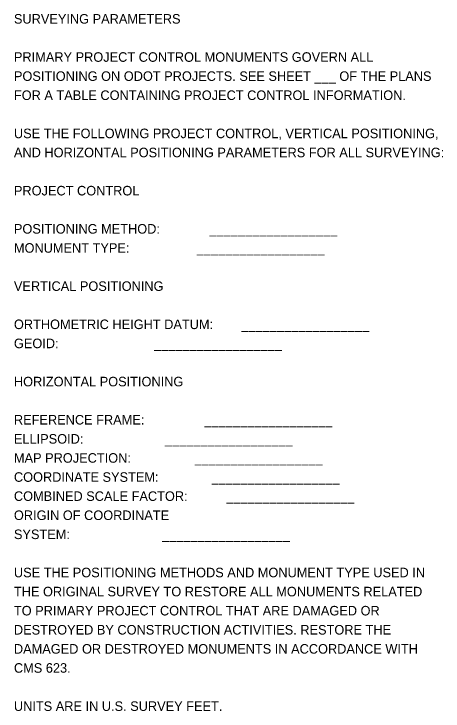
# Model space of a CAD drawing. Extents: x -6.7 to 44.8, y 0 to 42.6.
# Drawn here: x 38.55 to 44.85, y 32.38 to 42.6 of the extents above; entities that cross this region are included whole.
import ezdxf

# ---------------------------------------------------------------- set-up
doc = ezdxf.new("R2010")
doc.units = 0
doc.layers.add('SH_Text', color=7, linetype='Continuous')

msp = doc.modelspace()

# ---------------------------------------------------------------- texts
at = {"layer": 'SH_Text'}
for s, p in [('SURVEYING PARAMETERS', (38.553, 42.462)), ('PRIMARY PROJECT CONTROL MONUMENTS GOVERN ALL', (38.553, 41.902)), ('POSITIONING ON ODOT PROJECTS. SEE SHEET ___ OF THE PLANS', (38.553, 41.622)), ('FOR A TABLE CONTAINING PROJECT CONTROL INFORMATION.', (38.553, 41.342)), ('USE THE FOLLOWING PROJECT CONTROL, VERTICAL POSITIONING,', (38.553, 40.782)), ('AND HORIZONTAL POSITIONING PARAMETERS FOR ALL SURVEYING:', (38.553, 40.502)), ('PROJECT CONTROL', (38.553, 39.942)), ('POSITIONING METHOD:              __________________', (38.553, 39.382)), ('MONUMENT TYPE:                   __________________', (38.553, 39.102)), ('VERTICAL POSITIONING', (38.553, 38.542)), ('ORTHOMETRIC HEIGHT DATUM:        __________________', (38.553, 37.982)), ('GEOID:                           __________________', (38.553, 37.702)), ('HORIZONTAL POSITIONING', (38.553, 37.142)), ('REFERENCE FRAME:                 __________________', (38.553, 36.582)), ('ELLIPSOID:                       __________________', (38.553, 36.302)), ('MAP PROJECTION:                  __________________', (38.553, 36.022)), ('COORDINATE SYSTEM:               __________________', (38.553, 35.742)), ('COMBINED SCALE FACTOR:           __________________', (38.553, 35.462)), ('ORIGIN OF COORDINATE', (38.553, 35.182)), ('SYSTEM:                          __________________', (38.553, 34.902)), ('USE THE POSITIONING METHODS AND MONUMENT TYPE USED IN', (38.553, 34.342)), ('THE ORIGINAL SURVEY TO RESTORE ALL MONUMENTS RELATED', (38.553, 34.062)), ('TO PRIMARY PROJECT CONTROL THAT ARE DAMAGED OR', (38.553, 33.782)), ('DESTROYED BY CONSTRUCTION ACTIVITIES. RESTORE THE', (38.553, 33.502)), ('DAMAGED OR DESTROYED MONUMENTS IN ACCORDANCE WITH', (38.553, 33.222)), ('CMS 623.', (38.553, 32.942)), ('UNITS ARE IN U.S. SURVEY FEET.', (38.553, 32.382))]:
    msp.add_text(s, height=0.14, dxfattribs=at).set_placement(p)

doc.saveas('drawing.dxf')
